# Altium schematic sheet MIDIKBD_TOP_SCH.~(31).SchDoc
size A4
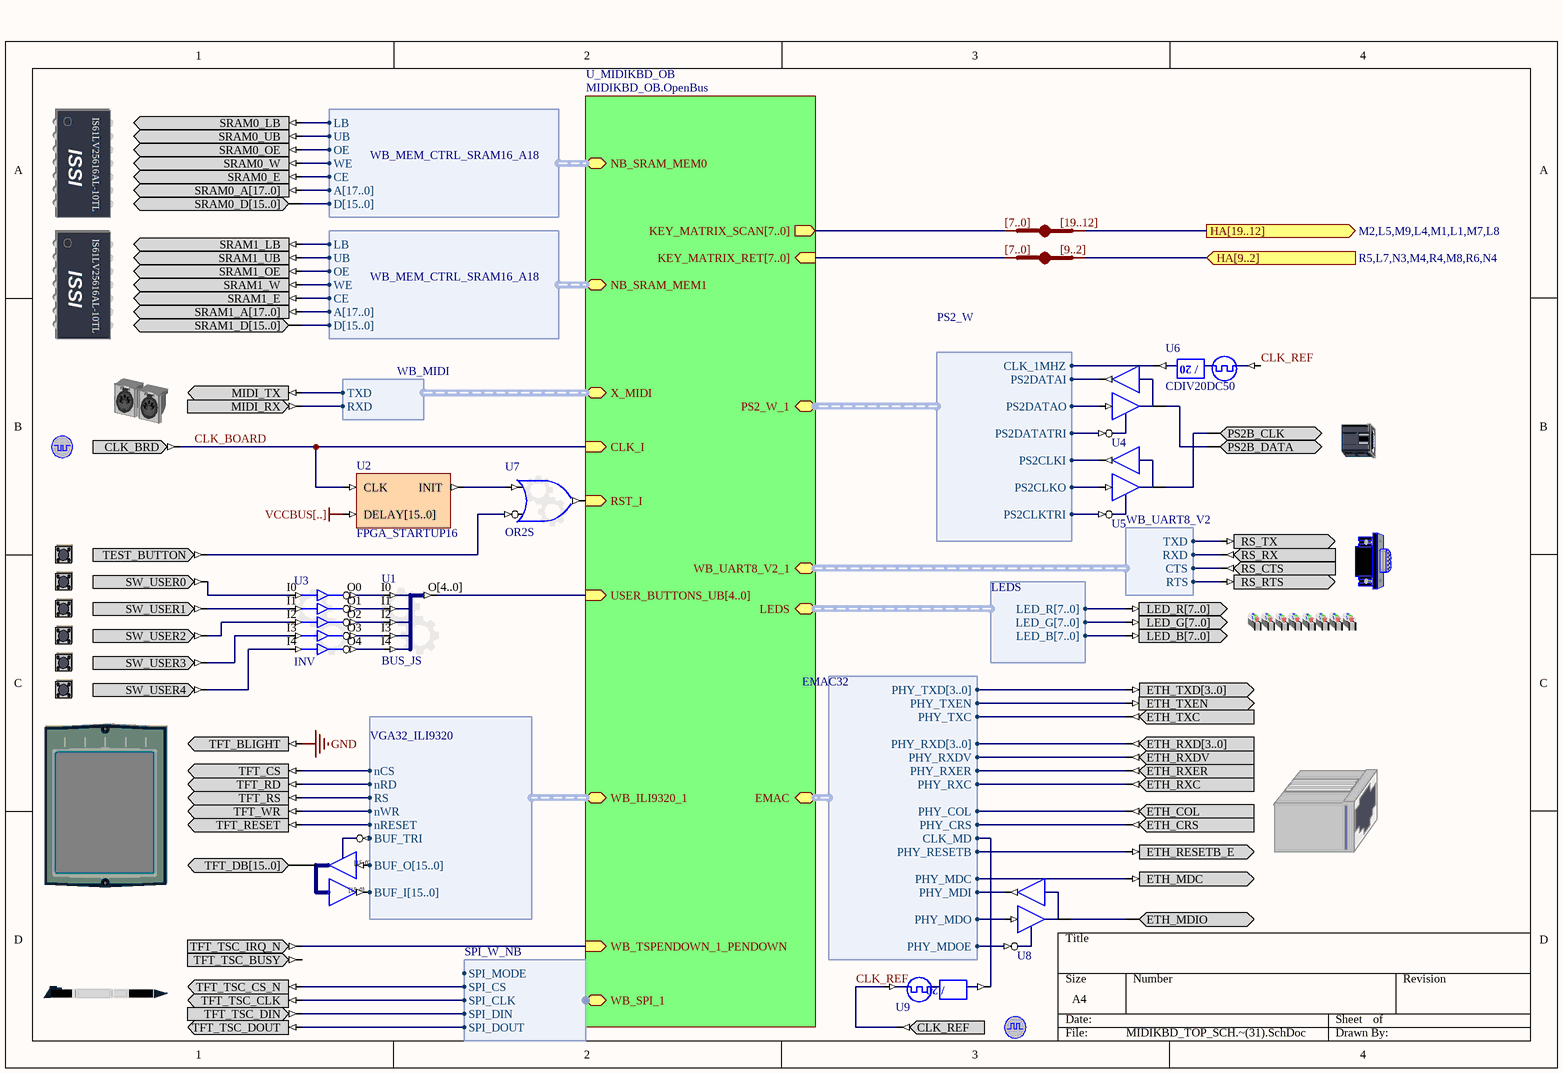
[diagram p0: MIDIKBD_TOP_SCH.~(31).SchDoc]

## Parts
(Parts that share a designator on the sheet are numbered #1, #2 ... from top to bottom, then left to right.)
?#1  SRAM0  (value not drawn)
?#2  SRAM1  (value not drawn)
?#3  MIDI  (value not drawn)
?#4  PS2B  (value not drawn)
?#5  CLOCK_BOARD  (value not drawn)
?#6  RS232CNTR  (value not drawn)
?#7  TEST_BUTTON  (value not drawn)
?#8  USER_BUTTON0  (value not drawn)
?#9  USER_BUTTON1  (value not drawn)
?#10  LEDS_RGB  (value not drawn)
?#11  USER_BUTTON2  (value not drawn)
?#12  USER_BUTTON3  (value not drawn)
?#13  USER_BUTTON4  (value not drawn)
?#14  ETH_PHY  (value not drawn)
?#15  TFT_LCD  (value not drawn)
?#16  TOUCH_SCREEN_PEN  (value not drawn)
?#17  CLOCK_REFERENCE  (value not drawn)
JB_AUTO?#1  IndexA: [7..0]  IndexB: [19..12]  (hidden comment: JB)
JB_AUTO?#2  IndexA: [7..0]  IndexB: [9..2]  (hidden comment: JB)
TFT_IOBUF  IOBUF16B  (value not drawn)
U1  BUS_JS
U2  FPGA_STARTUP16
U3  INV
U4  IOBUF  (value not drawn)
U5  IOBUF  (value not drawn)
U6  CDIV20DC50
U7  OR2S
U8  IOBUF  (value not drawn)
U9  CDIV20DC50  (value not drawn)

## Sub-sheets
U_MIDIKBD_OB = MIDIKBD_OB.OpenBus: RST_I (in), CLK_I (in), LEDS (harness LEDS), X_MIDI (harness WB_MIDI), USER_BUTTONS_UB[4..0] (in), NB_SRAM_MEM0 (harness WB_MEM_CTRL_SRAM16_A18), NB_SRAM_MEM1 (harness WB_MEM_CTRL_SRAM16_A18), PS2_W_1 (harness PS2_W), WB_ILI9320_1 (harness VGA32_ILI9320), EMAC (harness EMAC32), WB_TSPENDOWN_1_PENDOWN (in), WB_SPI_1 (harness SPI_W_NB), WB_UART8_V2_1 (harness WB_UART8_V2), KEY_MATRIX_SCAN[7..0] (out), KEY_MATRIX_RET[7..0] (in)

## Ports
HA[9..2] (in, see R5,L7,N3,M4,R4,M8,R6,N4), HA[19..12] (out, see M2,L5,M9,L4,M1,L1,M7,L8)

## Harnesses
LEDS: LED_R[7..0], LED_G[7..0], LED_B[7..0]
WB_MIDI: RXD, TXD
WB_MEM_CTRL_SRAM16_A18: D[15..0], A[17..0], CE, WE, OE, UB, LB
PS2_W: PS2CLKTRI, PS2CLKO, PS2CLKI, PS2DATATRI, PS2DATAO, PS2DATAI, CLK_1MHZ
VGA32_ILI9320: BUF_TRI, BUF_O[15..0], BUF_I[15..0], nRESET, nWR, RS, nRD, nCS
EMAC32: PHY_TXD[3..0], PHY_TXEN, PHY_TXC, PHY_RXD[3..0], PHY_RXDV, PHY_RXER, PHY_RXC, PHY_COL, PHY_CRS, PHY_RESETB, PHY_MDC, PHY_MDOE, PHY_MDO, PHY_MDI, CLK_MD
SPI_W_NB: SPI_DOUT, SPI_DIN, SPI_CLK, SPI_CS, SPI_MODE
WB_UART8_V2: TXD, RXD, CTS, RTS

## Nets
GND: ?#15.TFT_BLIGHT
VCCBUS[..]: U2.DELAY[15..0]
CLK_BOARD: ?#5.CLK_BRD U2.CLK ; sheet U_MIDIKBD_OB/CLK_I
CLK_REF: ?#17.CLK_REF U6.CLKIN U9.CLKIN
Net?#1_SRAM0_E: ?#1.SRAM0_E ; sheet U_MIDIKBD_OB/NB_SRAM_MEM0.CE
Net?#1_SRAM0_LB: ?#1.SRAM0_LB ; sheet U_MIDIKBD_OB/NB_SRAM_MEM0.LB
Net?#1_SRAM0_OE: ?#1.SRAM0_OE ; sheet U_MIDIKBD_OB/NB_SRAM_MEM0.OE
Net?#1_SRAM0_UB: ?#1.SRAM0_UB ; sheet U_MIDIKBD_OB/NB_SRAM_MEM0.UB
Net?#1_SRAM0_W: ?#1.SRAM0_W ; sheet U_MIDIKBD_OB/NB_SRAM_MEM0.WE
Net?#2_SRAM1_E: ?#2.SRAM1_E ; sheet U_MIDIKBD_OB/NB_SRAM_MEM1.CE
Net?#2_SRAM1_LB: ?#2.SRAM1_LB ; sheet U_MIDIKBD_OB/NB_SRAM_MEM1.LB
Net?#2_SRAM1_OE: ?#2.SRAM1_OE ; sheet U_MIDIKBD_OB/NB_SRAM_MEM1.OE
Net?#2_SRAM1_UB: ?#2.SRAM1_UB ; sheet U_MIDIKBD_OB/NB_SRAM_MEM1.UB
Net?#2_SRAM1_W: ?#2.SRAM1_W ; sheet U_MIDIKBD_OB/NB_SRAM_MEM1.WE
Net?#3_MIDI_RX: ?#3.MIDI_RX ; sheet U_MIDIKBD_OB/X_MIDI.RXD
Net?#3_MIDI_TX: ?#3.MIDI_TX ; sheet U_MIDIKBD_OB/X_MIDI.TXD
Net?#4_PS2B_CLK: ?#4.PS2B_CLK U5.IO
Net?#4_PS2B_DATA: ?#4.PS2B_DATA U4.IO
Net?#6_RS_CTS: ?#6.RS_CTS ; sheet U_MIDIKBD_OB/WB_UART8_V2_1.CTS
Net?#6_RS_RTS: ?#6.RS_RTS ; sheet U_MIDIKBD_OB/WB_UART8_V2_1.RTS
Net?#6_RS_RX: ?#6.RS_RX ; sheet U_MIDIKBD_OB/WB_UART8_V2_1.RXD
Net?#6_RS_TX: ?#6.RS_TX ; sheet U_MIDIKBD_OB/WB_UART8_V2_1.TXD
Net?#7_TEST_BUTTON: ?#7.TEST_BUTTON U7.I1
Net?#8_SW_USER0: ?#8.SW_USER0 U3.I0
Net?#9_SW_USER1: ?#9.SW_USER1 U3.I1
Net?#11_SW_USER2: ?#11.SW_USER2 U3.I2
Net?#12_SW_USER3: ?#12.SW_USER3 U3.I3
Net?#13_SW_USER4: ?#13.SW_USER4 U3.I4
Net?#14_ETH_COL: ?#14.ETH_COL ; sheet U_MIDIKBD_OB/EMAC.PHY_COL
Net?#14_ETH_CRS: ?#14.ETH_CRS ; sheet U_MIDIKBD_OB/EMAC.PHY_CRS
Net?#14_ETH_MDC: ?#14.ETH_MDC ; sheet U_MIDIKBD_OB/EMAC.PHY_MDC
Net?#14_ETH_MDIO: ?#14.ETH_MDIO U8.IO
Net?#14_ETH_RESETB_E: ?#14.ETH_RESETB_E ; sheet U_MIDIKBD_OB/EMAC.PHY_RESETB
Net?#14_ETH_RXC: ?#14.ETH_RXC ; sheet U_MIDIKBD_OB/EMAC.PHY_RXC
Net?#14_ETH_RXDV: ?#14.ETH_RXDV ; sheet U_MIDIKBD_OB/EMAC.PHY_RXDV
Net?#14_ETH_RXER: ?#14.ETH_RXER ; sheet U_MIDIKBD_OB/EMAC.PHY_RXER
Net?#14_ETH_TXC: ?#14.ETH_TXC ; sheet U_MIDIKBD_OB/EMAC.PHY_TXC
Net?#14_ETH_TXEN: ?#14.ETH_TXEN ; sheet U_MIDIKBD_OB/EMAC.PHY_TXEN
Net?#15_TFT_CS: ?#15.TFT_CS ; sheet U_MIDIKBD_OB/WB_ILI9320_1.nCS
Net?#15_TFT_DB[15..0]: ?#15.TFT_DB[15..0] TFT_IOBUF.IO[15..0]
Net?#15_TFT_RD: ?#15.TFT_RD ; sheet U_MIDIKBD_OB/WB_ILI9320_1.nRD
Net?#15_TFT_RESET: ?#15.TFT_RESET ; sheet U_MIDIKBD_OB/WB_ILI9320_1.nRESET
Net?#15_TFT_RS: ?#15.TFT_RS ; sheet U_MIDIKBD_OB/WB_ILI9320_1.RS
Net?#15_TFT_WR: ?#15.TFT_WR ; sheet U_MIDIKBD_OB/WB_ILI9320_1.nWR
Net?#16_TFT_TSC_CLK: ?#16.TFT_TSC_CLK ; sheet U_MIDIKBD_OB/WB_SPI_1.SPI_CLK
Net?#16_TFT_TSC_CS_N: ?#16.TFT_TSC_CS_N ; sheet U_MIDIKBD_OB/WB_SPI_1.SPI_CS
Net?#16_TFT_TSC_DIN: ?#16.TFT_TSC_DIN ; sheet U_MIDIKBD_OB/WB_SPI_1.SPI_DIN
Net?#16_TFT_TSC_DOUT: ?#16.TFT_TSC_DOUT ; sheet U_MIDIKBD_OB/WB_SPI_1.SPI_DOUT
Net?#16_TFT_TSC_IRQ_N: ?#16.TFT_TSC_IRQ_N ; sheet U_MIDIKBD_OB/WB_TSPENDOWN_1_PENDOWN
NetTFT_IOBUF_T: TFT_IOBUF.T ; sheet U_MIDIKBD_OB/WB_ILI9320_1.BUF_TRI
NetU1_I0: U1.I0 U3.O0
NetU1_I1: U1.I1 U3.O1
NetU1_I2: U1.I2 U3.O2
NetU1_I3: U1.I3 U3.O3
NetU1_I4: U1.I4 U3.O4
NetU2_INIT: U2.INIT U7.I0
NetU4_I: U4.I ; sheet U_MIDIKBD_OB/PS2_W_1.PS2DATAO
NetU4_O: U4.O ; sheet U_MIDIKBD_OB/PS2_W_1.PS2DATAI
NetU4_T: U4.T ; sheet U_MIDIKBD_OB/PS2_W_1.PS2DATATRI
NetU5_I: U5.I ; sheet U_MIDIKBD_OB/PS2_W_1.PS2CLKO
NetU5_O: U5.O ; sheet U_MIDIKBD_OB/PS2_W_1.PS2CLKI
NetU5_T: U5.T ; sheet U_MIDIKBD_OB/PS2_W_1.PS2CLKTRI
NetU6_CLKDV: U6.CLKDV ; sheet U_MIDIKBD_OB/PS2_W_1.CLK_1MHZ
NetU7_O: U7.O ; sheet U_MIDIKBD_OB/RST_I
NetU8_I: U8.I ; sheet U_MIDIKBD_OB/EMAC.PHY_MDO
NetU8_O: U8.O ; sheet U_MIDIKBD_OB/EMAC.PHY_MDI
NetU8_T: U8.T ; sheet U_MIDIKBD_OB/EMAC.PHY_MDOE
NetU9_CLKDV: U9.CLKDV ; sheet U_MIDIKBD_OB/EMAC.CLK_MD

Not connected (* = marked no-connect by the designer): ?#1 SRAM0_A[17..0] SRAM0_D[15..0]; ?#2 SRAM1_A[17..0] SRAM1_D[15..0]; ?#10 LED_B[7..0] LED_G[7..0] LED_R[7..0]; ?#14 ETH_RXD[3..0] ETH_TXD[3..0]; ?#16 TFT_TSC_BUSY; JB_AUTO?#1 A[0..0] B[0..0]; JB_AUTO?#2 A[0..0] B[0..0]; TFT_IOBUF I[15..0] O[15..0]; U1 O[4..0]

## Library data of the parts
?#1 = SRAM0: Free Static RAM - Daughterboard; PortComponent: True
?#2 = SRAM1: Free Static RAM - Daughterboard; PortComponent: True
?#3 = MIDI: MIDI Connector; PortComponent: True
?#4 = PS2B: Key Board PS2 Connector; PortComponent: True
?#5 = CLOCK_BOARD: Global System Clock Supply; PortComponent: True
?#6 = RS232CNTR: DCE Serial Port Connector; PortComponent: True
?#7 = TEST_BUTTON: Test / Reset Button; PortComponent: True
?#8 = USER_BUTTON0: Generic User Button; PortComponent: True
?#9 = USER_BUTTON1: Generic User Button; PortComponent: True
?#10 = LEDS_RGB: LEDS RGB; PortComponent: True
?#11 = USER_BUTTON2: Generic User Button; PortComponent: True
?#12 = USER_BUTTON3: Generic User Button; PortComponent: True
?#13 = USER_BUTTON4: Generic User Button; PortComponent: True
?#14 = ETH_PHY: Ethernet PHY-interface; PortComponent: True
?#15 = TFT_LCD: TFT LCD Panel; PortComponent: True
?#16 = TFT_PEN: Touch Screen Pen Control; PortComponent: True
?#17 = CLOCK_REFERENCE: Global System Clock Reference Supply; PortComponent: True
JB_AUTO?#1 JB_AUTO?#2 = JB: System BUS Joiner
TFT_IOBUF = IOBUF16B: 16-Bit Input/Output Buffer, Bus Version; SubClass: IOBUF; Enable: Low; Control: Common Control T; PortSize: 16; ArchiveName: GENERIC; VHDLIB_SIM: GENERIC_LIB
U1 = BUS_JS: Configurable Bus Joiner/Splitter; ConfiguratorName: GENERIC_BUS_JS; ConfigurationParameters: {}Version[1.1]{}SplitterJoinerType[Joiner]{}SignalCount[5]{}SignalWidth0[1]{}GapBelow0[1000000]{}ConnectionType0[Pin]{}SignalWidth1[1]{}GapBelow1[1000000]{}ConnectionType1[Pin]{}SignalWidth2[1]{}GapBelow2[1000000]{}ConnectionType2[Pin]{}SignalWidth3[1]{}GapBelow3[1000000]{}ConnectionType3[Pin]{}SignalWidth4[1]{}GapBelow4[1000000]{}ConnectionType4[Pin]{}ShowPinNames[True]{}
U2 = FPGA_STARTUP16: FPGA Startup With 16 Bit Delay
U3 = INV: Configurable Inverter; ConfigurationParameters: {}Version[1.1]{}SignalCount[5]{}SignalWidth0[1]{}OutputOption0[Inverted]{}SignalWidth1[1]{}OutputOption1[Inverted]{}SignalWidth2[1]{}OutputOption2[Inverted]{}SignalWidth3[1]{}OutputOption3[Inverted]{}SignalWidth4[1]{}OutputOption4[Inverted]{}EnableMode[None]{}ShowPinNames[True]{}; ConfiguratorName: GENERIC_BUFFER
U4 U5 = IOBUF: Input/Output Buffer; Enable: Low; Control: Common Control T; ArchiveName: GENERIC; VHDLIB_SIM: GENERIC_LIB
U6 U9 = CDIV20DC50: Clock Divider by 20 with 50% Duty Cycle Output; DivisorRate: 20; DutyCycle: 50; ArchiveName: GENERIC; VHDLIB_SIM: GENERIC_LIB
U7 = GATE: Configurable Generic Gate; ConfiguratorName: GENERIC_GATE; ConfigurationParameters: {}Version[1.0]{}GateKind[OR]{}BusInput[False]{}GateInputType[Bit]{}GateOutputOption[Normal]{}BusWidth[8]{}RegisterOutputs[False]{}NegativeClockEdge[False]{}InputCount[2]{}InputInvert0[False]{}InputInvert1[True]{}
U8 = iobuf: Input/Output Buffer; Enable: Low; Control: Common Control T; ArchiveName: GENERIC; VHDLIB_SIM: GENERIC_LIB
